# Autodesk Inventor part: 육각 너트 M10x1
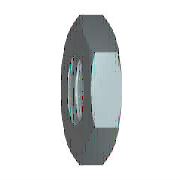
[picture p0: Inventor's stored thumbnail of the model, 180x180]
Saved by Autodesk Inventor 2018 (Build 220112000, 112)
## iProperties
Created: 2012-02
Part Number: 육각 너트 M10x1
Material: 스테인리스강
Description: 6각 가는 너트(모따기) - 제품 등급 A 및 B
Document SubType Name: Modeling
Standard: ISO 4035
Designer: mdu-01
Standard Revision: Third edition 1999-08-15
Standards Organization: ISO
Language: ko-KR
Size Designation: M10
Categories: <MemberInstance><Categories><Category DisplayName="조임쇠" InternalName="e4da775c-781d-43d5-af7c-5136215cf5a6" Mnemonic="FSTN"><Category DisplayName="너트" InternalN
Density: 7.75 g/cm^3
Appearance: 반광택
IsCustomPart: 1
Author: mdu-01
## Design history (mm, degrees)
sketch "스케치1"
  geometry: L1 (-9.238, 0)-(-4.619, 8); L2 (-4.619, 8)-(4.619, 8); L3 (4.619, 8)-(9.238, 0); L4 (9.238, 0)-(4.619, -8); L5 (4.619, -8)-(-4.619, -8); L6 (-4.619, -8)-(-9.238, 0); 2 further points
  constraints: 12 end point, 1 coincident, 1 horizontal, 11 other
  dimensions: "d0" = 18.47521 distance of L3.end L1.start (= 1.1547 x SW)
extrude "본체" new body sketch "스케치1" distance "d1" = 5 (= KOH); taper "d2" = 0 deg
sketch "스케치2"
  geometry: L1 (0, 4.619)-(0, 9.238) reference; L2 (0, 9.238)-(5, 9.238) reference; L3 (5, 4.619)-(5, 9.238) reference; L4 (-1, 0)-(6, 0) reference; L5 (1.119, 9.238)-(0, 7.3); L6 (3.881, 9.238)-(5, 7.3)
  constraints: 4 end point, 4 point on line
  dimensions: "d3" = 30 deg angle of L1 L5 (= ANG1); "d4" = 30 deg angle of L3 L6 (= ANG2); "d5" = 14.6 diameter of L5.end L4 (= SW0); "d6" = 14.6 diameter of L6.end L4 (= SW01)
revolve "모따기1" sketch "스케치2" stored, may be unused: angle "d7" = 90 deg
sketch "스케치3"
  geometry: 4 further points
  constraints: 1 coincident, 1 other
hole "스레드" sketch "스케치3" at (0, 0) diameter "d25" = 8.917; stored, may be unused: countersink angle "d29" = 82 deg, drill point angle "d31" = 118 deg; dims "d26" = 6, "d27" = 4, "d28" = 2, "d30" = 8
workaxis "Work Axis1"
workplane "Work Plane1"
body "Solid1"
chamfer "모따기2" distance "d8" = 0.8119 (= -0.5 x GD1 + 0.5 x NND); stored, may be unused: angle "d9" = 30 deg, second distance "d40" = 0.8119 (= -0.5 x GD1 + 0.5 x NND)
chamfer "모따기3" distance "d10" = 0.8119 (= -0.5 x GD1 + 0.5 x NND); stored, may be unused: angle "d11" = 30 deg, second distance "d41" = 0.8119 (= -0.5 x GD1 + 0.5 x NND)
other parameters: "ANG1" = 30 deg [user parameter; used in 1 equation term], "ANG2" = 30 deg [user parameter; used in 1 equation term], "KOH" = 5 [user parameter; used in 1 equation term], "SW" = 16 [user parameter; used in 2 equation terms], "SW0" = 14.6 [user parameter; used in 2 equation terms], "SW01" = 14.6 (= SW0) [user parameter; used in 1 equation term], "GD1" = 8.3762 (computed from THREADDIA, PTC, TOA) [user parameter; used in 4 equation terms], "d13" = 0, "d14" = 0, "d39" = 0, "d42" = 0, "GUL" = 0.8119 (= 0.541266 x PTC) [user parameter], "TPU" = 6.66667 (computed from PTC) [user parameter], "TOA" = 30 deg [user parameter; used in 1 equation term], "PTC" = 1.5 [user parameter; used in 4 equation terms], "E0" = 18.48 (= 1.155 x SW) [user parameter], "GAL" = 0.8119 (= 0.541266 x PTC) [user parameter]
